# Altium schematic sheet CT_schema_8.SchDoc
size 147 x 119 mm
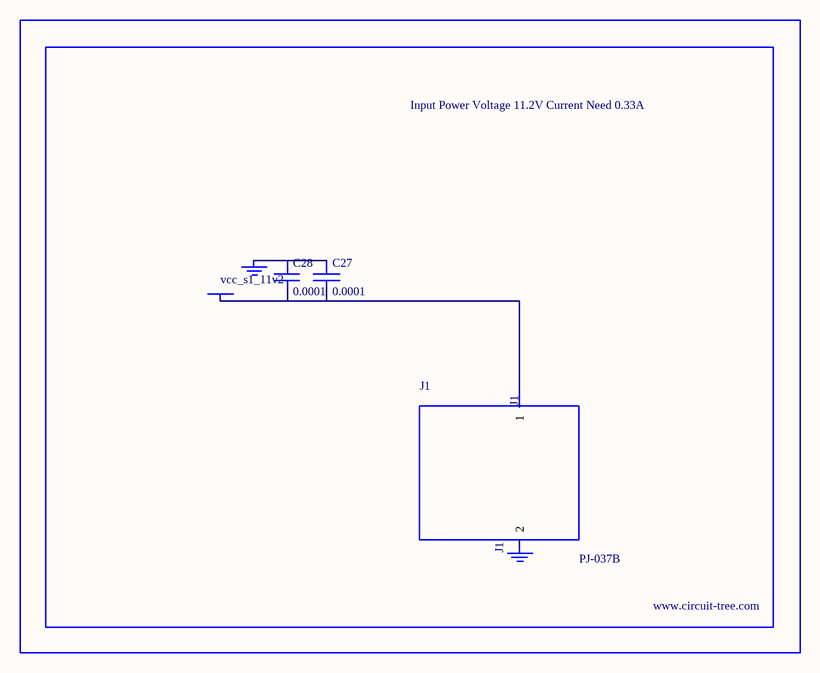
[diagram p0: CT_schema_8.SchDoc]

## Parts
BORDER7  (no value)
C27  0.0001  [EXV-9H]
C28  0.0001  [EXV-9H]
GND_INSTANCE_7_0  (no value)
GND_INSTANCE_7_1  (no value)
J1  PJ-037B  [PJ-037B_PACKAGE]
POWER_INSTANCE_7_0  vcc_s1_11v2

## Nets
NetC27_1: C27.1 C28.1 GND_INSTANCE_7_0.0(GND)
NetC27_2: C27.2 C28.2 J1.1 POWER_INSTANCE_7_0.0(PWR)

Not connected (* = marked no-connect by the designer): GND_INSTANCE_7_1 0(GND); J1 2

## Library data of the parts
BORDER7 = BORDER_PAGE7
C27 C28 = EDK107M035A9HAA
GND_INSTANCE_7_0 GND_INSTANCE_7_1 = GND
POWER_INSTANCE_7_0 = PWR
